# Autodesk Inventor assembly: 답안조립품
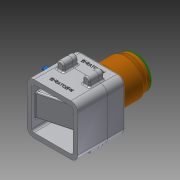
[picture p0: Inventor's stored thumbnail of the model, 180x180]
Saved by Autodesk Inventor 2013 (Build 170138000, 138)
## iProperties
Created: 2018-01
Part Number: 답안조립품
Document SubType Name: Assembly
Designer: Administrator
Author: Administrator
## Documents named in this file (9)
- C:\Users\Administrator\Desktop\480108V1023\답안조립품.iam
- C:\Users\Administrator\Desktop\480108V1023\본체.ipt
- C:\Users\Administrator\Desktop\480108V1023\핸들축.ipt
- C:\Users\Administrator\Desktop\480108V1023\핸들.ipt
- C:\Users\Administrator\Desktop\480108V1023\볼트 M3x12.ipt
- C:\Users\Administrator\Desktop\480108V1023\본체커버.ipt
- C:\Users\Administrator\Desktop\480108V1023\볼트 M4x12.ipt
- C:\Users\Administrator\Desktop\480108V1023\용기.ipt
- C:\Users\Administrator\Desktop\480108V1023\용기캡.ipt
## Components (2 placed, 2 different names)
1. 핸들축:1
2. 핸들:1
